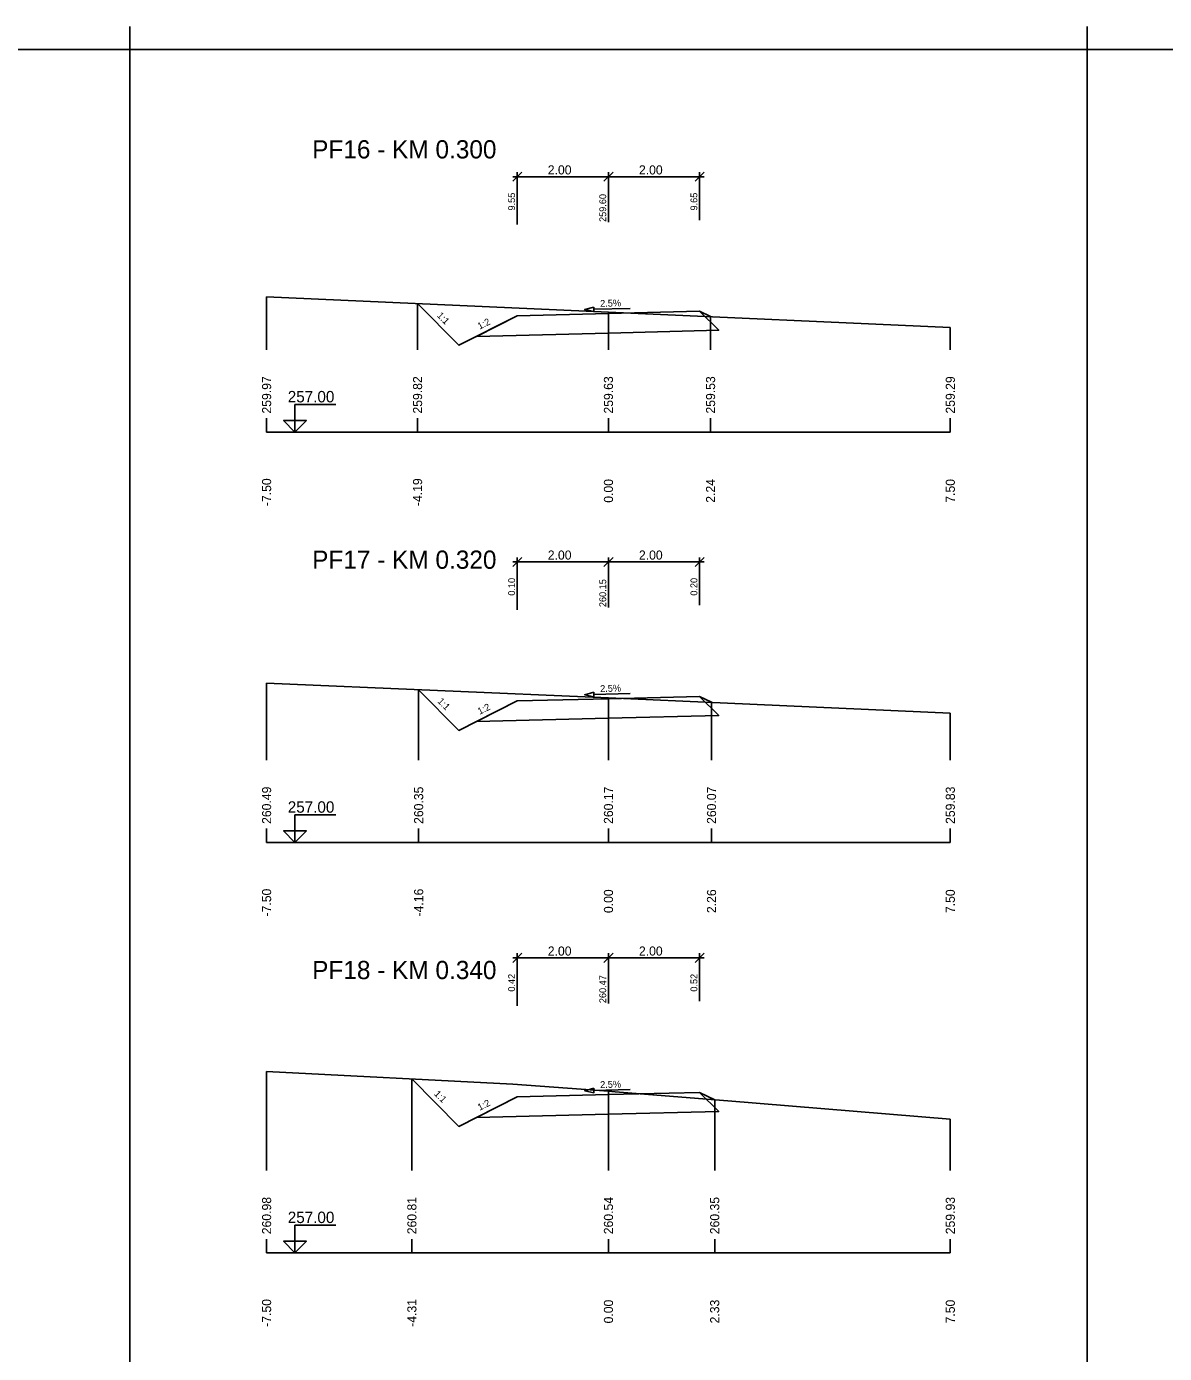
# Model space of a CAD drawing. Extents: x -1895 to 2525, y -19 to 585.
# Drawn here: x -862.6 to -613, y 293.9 to 584.9 of the extents above; entities that cross this region are included whole.
import ezdxf

# ---------------------------------------------------------------- set-up
doc = ezdxf.new("R2010")
doc.units = 0
for name, color, linetype in [('KOTA', 7, 'Continuous'), ('KOTA_DELKY', 7, 'Continuous'), ('KOTA_DELKY_CONT', 7, 'Continuous'), ('NS_TELESO_VOZOVKY', 7, 'Continuous'), ('NS_V_PF', 7, 'Continuous'), ('REZY_PF_PUVODNI', 7, 'Continuous'), ('SESTAVY_REZU_PF', 7, 'Continuous'), ('SKLON', 7, 'Continuous'), ('SVK', 7, 'Continuous')]:
    doc.layers.add(name, color=color, linetype=linetype)

msp = doc.modelspace()

# ---------------------------------------------------------------- linework, layer by layer
for p, q in [((-839.95, 584.93), (-839.95, 574.93)), ((-839.95, 584.93), (-839.95, 574.93)), ((-629.95, 584.93), (-629.95, 574.93)), ((-629.95, 584.93), (-629.95, 574.93)), ((-834.95, 579.93), (-844.95, 579.93)), ((-834.95, 579.93), (-844.95, 579.93)), ((-624.95, 579.93), (-634.95, 579.93)), ((-624.95, 579.93), (-634.95, 579.93))]:
    msp.add_line(p, q)
for points in [[(-1049.95, 579.93), (-839.95, 579.93), (-839.95, 282.93), (-1049.95, 282.93)], [(-839.95, 579.93), (-629.95, 579.93), (-629.95, 282.93), (-839.95, 282.93)], [(-629.95, 579.93), (-419.95, 579.93), (-419.95, 282.93), (-629.95, 282.93)]]:
    msp.add_lwpolyline(points, close=True)
at = {"layer": 'KOTA'}
for points in [[(-803.73, 498.5), (-806.23, 498.5), (-803.73, 496), (-803.73, 502), (-794.73, 502)], [(-803.73, 496), (-801.23, 498.5), (-803.73, 498.5)], [(-803.73, 408.5), (-806.23, 408.5), (-803.73, 406), (-803.73, 412), (-794.73, 412)], [(-803.73, 406), (-801.23, 408.5), (-803.73, 408.5)], [(-803.73, 318.5), (-806.23, 318.5), (-803.73, 316), (-803.73, 322), (-794.73, 322)], [(-803.73, 316), (-801.23, 318.5), (-803.73, 318.5)]]:
    msp.add_lwpolyline(points, dxfattribs=at)
at = {"layer": 'KOTA_DELKY'}
for points in [[(-755.95, 550.99), (-753.95, 552.99)], [(-754.95, 541.49), (-754.95, 552.99)], [(-735.95, 550.99), (-733.95, 552.99)], [(-735.95, 550.99), (-733.95, 552.99)], [(-734.95, 541.99), (-734.95, 552.99)], [(-734.95, 541.99), (-734.95, 552.99)], [(-715.95, 550.99), (-713.95, 552.99)], [(-714.95, 542.49), (-714.95, 552.99)], [(-755.95, 551.99), (-733.95, 551.99)], [(-735.95, 551.99), (-713.95, 551.99)], [(-755.95, 466.51), (-753.95, 468.51)], [(-755.95, 467.51), (-733.95, 467.51)], [(-754.95, 457.01), (-754.95, 468.51)], [(-735.95, 466.51), (-733.95, 468.51)], [(-735.95, 466.51), (-733.95, 468.51)], [(-735.95, 467.51), (-713.95, 467.51)], [(-734.95, 457.51), (-734.95, 468.51)], [(-734.95, 457.51), (-734.95, 468.51)], [(-715.95, 466.51), (-713.95, 468.51)], [(-714.95, 458.01), (-714.95, 468.51)], [(-755.95, 379.66), (-753.95, 381.66)], [(-754.95, 370.16), (-754.95, 381.66)], [(-735.95, 379.66), (-733.95, 381.66)], [(-735.95, 379.66), (-733.95, 381.66)], [(-734.95, 370.66), (-734.95, 381.66)], [(-734.95, 370.66), (-734.95, 381.66)], [(-715.95, 379.66), (-713.95, 381.66)], [(-714.95, 371.16), (-714.95, 381.66)], [(-755.95, 380.66), (-733.95, 380.66)], [(-735.95, 380.66), (-713.95, 380.66)]]:
    msp.add_lwpolyline(points, dxfattribs=at)
at = {"layer": 'NS_TELESO_VOZOVKY'}
for points in [[(-734.95, 521.99), (-714.95, 522.49), (-714.95, 522.49), (-710.75, 518.3), (-734.95, 517.69), (-763.89, 516.97), (-754.95, 521.49), (-754.95, 521.49), (-734.95, 521.99)], [(-734.95, 437.51), (-714.95, 438.01), (-714.95, 438.01), (-710.75, 433.82), (-734.95, 433.21), (-763.89, 432.49), (-754.95, 437.01), (-754.95, 437.01), (-734.95, 437.51)], [(-734.95, 350.66), (-714.95, 351.16), (-714.95, 351.16), (-710.75, 346.96), (-734.95, 346.36), (-763.89, 345.63), (-754.95, 350.16), (-754.95, 350.16), (-734.95, 350.66)]]:
    msp.add_lwpolyline(points, dxfattribs=at)
at = {"layer": 'NS_V_PF'}
for points in [[(-776.83, 524.19), (-767.76, 515.02), (-754.95, 521.49), (-754.95, 521.49), (-734.95, 521.99), (-714.95, 522.49), (-714.95, 522.49), (-712.55, 521.3)], [(-776.59, 439.46), (-767.76, 430.54), (-754.95, 437.01), (-754.95, 437.01), (-734.95, 437.51), (-714.95, 438.01), (-714.95, 438.01), (-712.34, 436.71)], [(-778.08, 354.11), (-767.76, 343.68), (-754.95, 350.16), (-754.95, 350.16), (-734.95, 350.66), (-714.95, 351.16), (-714.95, 351.16), (-711.64, 349.5)]]:
    msp.add_lwpolyline(points, dxfattribs=at)
at = {"layer": 'REZY_PF_PUVODNI'}
for points in [[(-809.95, 525.68), (-734.95, 522.3), (-659.95, 518.93)], [(-809.95, 440.88), (-734.95, 437.68), (-708.85, 436.56), (-659.95, 434.3)], [(-809.95, 355.77), (-755.94, 352.96), (-734.95, 351.39), (-733.48, 351.28), (-708.79, 349.27), (-659.95, 345.28)]]:
    msp.add_lwpolyline(points, dxfattribs=at)
at = {"layer": 'SESTAVY_REZU_PF'}
for points in [[(-809.95, 496), (-659.95, 496)], [(-809.95, 406), (-659.95, 406)], [(-809.95, 316), (-659.95, 316)]]:
    msp.add_lwpolyline(points, dxfattribs=at)
at = {"layer": 'SKLON'}
for points in [[(-738.16, 523.41), (-740.15, 522.86), (-738.14, 522.41), (-738.16, 523.41)], [(-738.15, 522.91), (-730.15, 523.11)], [(-738.16, 438.93), (-740.15, 438.38), (-738.14, 437.93), (-738.16, 438.93)], [(-738.15, 438.43), (-730.15, 438.63)], [(-738.16, 352.08), (-740.15, 351.53), (-738.14, 351.08), (-738.16, 352.08)], [(-738.15, 351.58), (-730.15, 351.78)]]:
    msp.add_lwpolyline(points, dxfattribs=at)
at = {"layer": 'SVK'}
for points in [[(-809.95, 514), (-809.95, 525.68)], [(-776.83, 514), (-776.83, 524.19)], [(-734.95, 514), (-734.95, 522.3)], [(-712.55, 514), (-712.55, 521.3)], [(-659.95, 514), (-659.95, 518.93)], [(-809.95, 496), (-809.95, 499)], [(-776.83, 496), (-776.83, 499)], [(-734.95, 496), (-734.95, 499)], [(-712.55, 496), (-712.55, 499)], [(-659.95, 496), (-659.95, 499)], [(-809.95, 424), (-809.95, 440.88)], [(-776.59, 424), (-776.59, 439.46)], [(-734.95, 424), (-734.95, 437.68)], [(-712.34, 424), (-712.34, 436.71)], [(-659.95, 424), (-659.95, 434.3)], [(-809.95, 406), (-809.95, 409)], [(-776.59, 406), (-776.59, 409)], [(-734.95, 406), (-734.95, 409)], [(-712.34, 406), (-712.34, 409)], [(-659.95, 406), (-659.95, 409)], [(-809.95, 334), (-809.95, 355.77)], [(-778.08, 334), (-778.08, 354.11)], [(-734.95, 334), (-734.95, 351.39)], [(-711.64, 334), (-711.64, 349.5)], [(-659.95, 334), (-659.95, 345.28)], [(-809.95, 316), (-809.95, 319)], [(-778.08, 316), (-778.08, 319)], [(-734.95, 316), (-734.95, 319)], [(-711.64, 316), (-711.64, 319)], [(-659.95, 316), (-659.95, 319)]]:
    msp.add_lwpolyline(points, dxfattribs=at)

# ---------------------------------------------------------------- texts
at = {"layer": 'KOTA'}
for p in [(-805.31, 502.5), (-805.31, 412.5), (-805.31, 322.5)]:
    msp.add_text('257.00', height=2.5, dxfattribs=at).set_placement(p)
at = {"layer": 'KOTA_DELKY'}
for p in [(-748.26, 552.49), (-728.26, 552.49), (-748.26, 468.01), (-728.26, 468.01), (-748.26, 381.16), (-728.26, 381.16)]:
    msp.add_text('2.00', height=2, dxfattribs=at).set_placement(p)
at = {"layer": 'KOTA_DELKY_CONT'}
for s, p in [('9.55', (-755.45, 544.58)), ('259.60', (-735.45, 542.07)), ('9.65', (-715.45, 544.58)), ('0.10', (-755.45, 460.1)), ('260.15', (-735.45, 457.59)), ('0.20', (-715.45, 460.1)), ('0.42', (-755.45, 373.25)), ('260.47', (-735.45, 370.73)), ('0.52', (-715.45, 373.25))]:
    msp.add_text(s, height=1.5, rotation=90, dxfattribs=at).set_placement(p)
at = {"layer": 'SESTAVY_REZU_PF'}
for s, p in [('PF16 - KM 0.300', (-799.95, 556)), ('PF17 - KM 0.320', (-799.95, 466)), ('PF18 - KM 0.340', (-799.95, 376))]:
    msp.add_text(s, height=4, dxfattribs=at).set_placement(p)
at = {"layer": 'SKLON'}
for s, rotation, p in [('2.5%', 1.4321, (-736.75, 523.45)), ('1:1', 314.7121, (-772.69, 521.43)), ('1:2', 26.8233, (-763.21, 518.44)), ('2.5%', 1.4321, (-736.75, 438.97)), ('1:1', 314.7121, (-772.57, 436.82)), ('1:2', 26.8233, (-763.21, 433.96)), ('2.5%', 1.4321, (-736.75, 352.11)), ('1:1', 314.7121, (-773.32, 350.72)), ('1:2', 26.8233, (-763.21, 347.1))]:
    msp.add_text(s, height=1.5, rotation=rotation, dxfattribs=at).set_placement(p)
at = {"layer": 'SVK'}
for s, p in [(' 259.97', (-808.95, 499.3)), (' 259.82', (-775.83, 499.3)), (' 259.63', (-733.95, 499.3)), (' 259.53', (-711.55, 499.3)), (' 259.29', (-658.95, 499.3)), (' -7.50', (-808.95, 479)), (' -4.19', (-775.83, 479)), ('  0.00', (-733.95, 479)), ('  2.24', (-711.55, 479)), ('  7.50', (-658.95, 479)), (' 260.49', (-808.95, 409.3)), (' 260.35', (-775.59, 409.3)), (' 260.17', (-733.95, 409.3)), (' 260.07', (-711.34, 409.3)), (' 259.83', (-658.95, 409.3)), (' -7.50', (-808.95, 389)), (' -4.16', (-775.59, 389)), ('  0.00', (-733.95, 389)), ('  2.26', (-711.34, 389)), ('  7.50', (-658.95, 389)), (' 260.98', (-808.95, 319.3)), (' 260.81', (-777.08, 319.3)), (' 260.54', (-733.95, 319.3)), (' 260.35', (-710.64, 319.3)), (' 259.93', (-658.95, 319.3)), (' -7.50', (-808.95, 299)), (' -4.31', (-777.08, 299)), ('  0.00', (-733.95, 299)), ('  7.50', (-658.95, 299)), ('  2.33', (-710.64, 299))]:
    msp.add_text(s, height=2, rotation=90, dxfattribs=at).set_placement(p)

doc.saveas('drawing.dxf')
